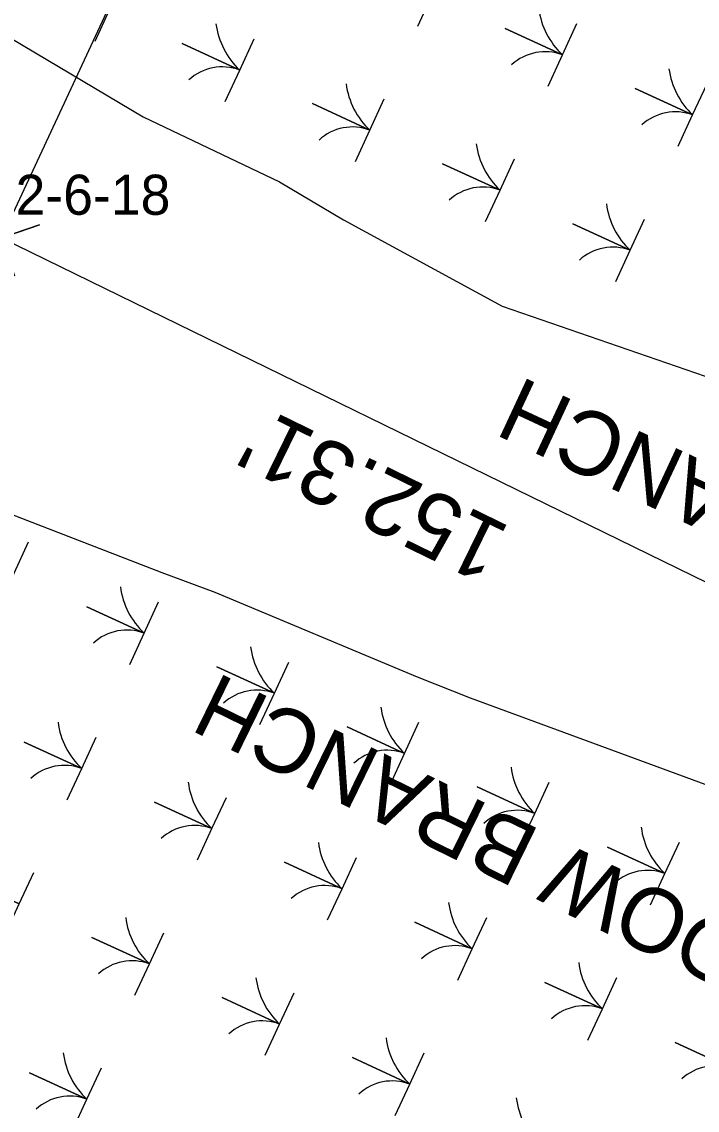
# Model space of a CAD drawing. Extents: x 2532037 to 2533565, y 713396 to 716867.
# Drawn here: x 2532899.5 to 2532941.6, y 715572.7 to 715640.6 of the extents above; entities that cross this region are included whole.
import ezdxf

# ---------------------------------------------------------------- set-up
doc = ezdxf.new("R2010")
doc.units = 0
for name, color, linetype in [('Exist DTM Spot Elevation Cogo Comment', 7, 'Continuous'), ('Exist Hydro Jurisdictional Stream or Body of Water', 7, 'Continuous'), ('Exist Hydro Stream or Body of Water Text', 7, 'Continuous'), ('Exist Property Corner CELL', 7, 'Continuous'), ('Exist Property Line', 7, 'Continuous'), ('Exist Property Line Text', 7, 'Continuous'), ('Exist Right of Way Line', 7, 'Continuous'), ('Scratch_Level_1', 7, 'Continuous')]:
    doc.layers.add(name, color=color, linetype=linetype)

msp = doc.modelspace()

# ---------------------------------------------------------------- linework, layer by layer
at = {"layer": 'Exist Hydro Jurisdictional Stream or Body of Water'}
for points in [[(2532806.944, 715649.86), (2532823.862, 715653.608), (2532826.936, 715654.78), (2532846.795, 715657.486), (2532848.935, 715657.763), (2532859.818, 715661.557), (2532865.255, 715655.34), (2532866.545, 715654.873), (2532867.828, 715654.527), (2532870.349, 715653.031), (2532883.272, 715647.025), (2532884.83, 715646.372), (2532885.882, 715645.762), (2532886.539, 715645.426), (2532889.693, 715644.068), (2532889.952, 715644.137), (2532891.522, 715643.982), (2532891.782, 715643.826), (2532896.496, 715640.921), (2532907.078, 715634.646), (2532915.587, 715630.595), (2532919.574, 715628.211), (2532929.47, 715622.835), (2532946.956, 715616.792)], [(2532799.821, 715621.688), (2532825.866, 715627.44), (2532828.419, 715628.003), (2532832.005, 715633.511), (2532832.017, 715633.527), (2532835.552, 715631.335), (2532845.081, 715630.726), (2532846.796, 715630.623), (2532853.018, 715629.166), (2532854.009, 715628.204), (2532858.784, 715626.141), (2532874.956, 715619.591), (2532887.027, 715614.556), (2532890.708, 715612.987), (2532908.235, 715606.211), (2532911.538, 715604.984), (2532924.18, 715599.711), (2532927.478, 715598.382), (2532943.534, 715592.488)]]:
    msp.add_lwpolyline(points, dxfattribs=at)
at = {"layer": 'Exist Property Corner CELL'}
msp.add_lwpolyline([(2532895.873, 715626.28), (2532900.602, 715627.904), (2532898.238, 715627.092), (2532897.425, 715629.457), (2532899.05, 715624.728)], dxfattribs=at)
at = {"layer": 'Exist Property Line'}
msp.add_line((2532898.238, 715627.092), (2533035.08, 715560.215), dxfattribs=at)
at = {"layer": 'Exist Right of Way Line'}
msp.add_line((2532748.017, 715304.207), (2532950.036, 715738.429), dxfattribs=at)
at = {"layer": 'Scratch_Level_1'}
for points in [[(2532924.214, 715640.31), (2532925.116, 715642.262), (2532921.534, 715643.916), (2532925.116, 715642.262), (2532926.017, 715644.215)], [(2532904.073, 715639.364), (2532904.974, 715641.317), (2532901.392, 715642.97), (2532904.974, 715641.317), (2532905.876, 715643.269)], [(2532932.336, 715636.561), (2532933.237, 715638.513), (2532929.655, 715640.167), (2532933.237, 715638.513), (2532934.138, 715640.465)], [(2532912.194, 715635.615), (2532913.096, 715637.567), (2532909.514, 715639.221), (2532913.096, 715637.567), (2532913.997, 715639.52)], [(2532940.457, 715632.811), (2532941.358, 715634.764), (2532937.777, 715636.417), (2532941.358, 715634.764), (2532942.26, 715636.716)], [(2532920.316, 715631.866), (2532921.217, 715633.818), (2532917.635, 715635.472), (2532921.217, 715633.818), (2532922.118, 715635.77)], [(2532928.437, 715628.116), (2532929.339, 715630.069), (2532925.757, 715631.722), (2532929.339, 715630.069), (2532930.24, 715632.021)], [(2532936.559, 715624.367), (2532937.46, 715626.319), (2532933.878, 715627.973), (2532937.46, 715626.319), (2532938.361, 715628.272)], [(2532898.117, 715604.22), (2532899.018, 715606.173), (2532895.436, 715607.826), (2532899.018, 715606.173), (2532899.92, 715608.125)], [(2532906.238, 715600.471), (2532907.14, 715602.423), (2532903.558, 715604.077), (2532907.14, 715602.423), (2532908.041, 715604.376)], [(2532914.36, 715596.721), (2532915.261, 715598.674), (2532911.679, 715600.327), (2532915.261, 715598.674), (2532916.163, 715600.626)], [(2532922.481, 715592.972), (2532923.383, 715594.924), (2532919.801, 715596.578), (2532923.383, 715594.924), (2532924.284, 715596.877)], [(2532902.34, 715592.026), (2532903.241, 715593.979), (2532899.659, 715595.632), (2532903.241, 715593.979), (2532904.143, 715595.931)], [(2532930.603, 715589.223), (2532931.504, 715591.175), (2532927.922, 715592.829), (2532931.504, 715591.175), (2532932.405, 715593.127)], [(2532910.461, 715588.277), (2532911.363, 715590.229), (2532907.781, 715591.883), (2532911.363, 715590.229), (2532912.264, 715592.182)], [(2532938.724, 715585.473), (2532939.626, 715587.426), (2532936.044, 715589.079), (2532939.626, 715587.426), (2532940.527, 715589.378)], [(2532918.583, 715584.528), (2532919.484, 715586.48), (2532915.902, 715588.134), (2532919.484, 715586.48), (2532920.386, 715588.432)], [(2532898.442, 715583.582), (2532899.343, 715585.534), (2532895.761, 715587.188), (2532899.343, 715585.534), (2532900.244, 715587.487)], [(2532926.704, 715580.778), (2532927.606, 715582.731), (2532924.024, 715584.384), (2532927.606, 715582.731), (2532928.507, 715584.683)], [(2532906.563, 715579.833), (2532907.464, 715581.785), (2532903.882, 715583.439), (2532907.464, 715581.785), (2532908.366, 715583.737)], [(2532934.826, 715577.029), (2532935.727, 715578.981), (2532932.145, 715580.635), (2532935.727, 715578.981), (2532936.628, 715580.934)], [(2532914.684, 715576.083), (2532915.586, 715578.036), (2532912.004, 715579.689), (2532915.586, 715578.036), (2532916.487, 715579.988)], [(2532942.947, 715573.28), (2532943.849, 715575.232), (2532940.267, 715576.886), (2532943.849, 715575.232), (2532944.75, 715577.184)], [(2532922.806, 715572.334), (2532923.707, 715574.286), (2532920.125, 715575.94), (2532923.707, 715574.286), (2532924.609, 715576.239)], [(2532902.665, 715571.388), (2532903.566, 715573.341), (2532899.984, 715574.994), (2532903.566, 715573.341), (2532904.467, 715575.293)]]:
    msp.add_lwpolyline(points, dxfattribs=at)
for centre, radius, start, end in [((2532936.524, 715642.018), 4.806, 187.34643, 226.84116), ((2532916.383, 715641.073), 4.806, 187.34643, 226.84116), ((2532932.153, 715635.636), 3.075, 69.35932, 132.75394), ((2532912.012, 715634.69), 3.075, 69.35932, 132.75394), ((2532944.646, 715638.269), 4.806, 187.34643, 226.84116), ((2532924.504, 715637.323), 4.806, 187.34643, 226.84116), ((2532940.275, 715631.886), 3.075, 69.35932, 132.75394), ((2532920.133, 715630.941), 3.075, 69.35932, 132.75394), ((2532932.626, 715633.574), 4.806, 187.34643, 226.84116), ((2532928.255, 715627.191), 3.075, 69.35932, 132.75394), ((2532940.747, 715629.825), 4.806, 187.34643, 226.84116), ((2532936.376, 715623.442), 3.075, 69.35932, 132.75394), ((2532910.427, 715605.929), 4.806, 187.34643, 226.84116), ((2532906.056, 715599.546), 3.075, 69.35932, 132.75394), ((2532918.548, 715602.179), 4.806, 187.34643, 226.84116), ((2532914.177, 715595.797), 3.075, 69.35932, 132.75394), ((2532926.67, 715598.43), 4.806, 187.34643, 226.84116), ((2532906.529, 715597.484), 4.806, 187.34643, 226.84116), ((2532922.299, 715592.047), 3.075, 69.35932, 132.75394), ((2532902.158, 715591.102), 3.075, 69.35932, 132.75394), ((2532934.791, 715594.681), 4.806, 187.34643, 226.84116), ((2532914.65, 715593.735), 4.806, 187.34643, 226.84116), ((2532930.42, 715588.298), 3.075, 69.35932, 132.75394), ((2532910.279, 715587.352), 3.075, 69.35932, 132.75394), ((2532942.913, 715590.931), 4.806, 187.34643, 226.84116), ((2532922.771, 715589.986), 4.806, 187.34643, 226.84116), ((2532938.542, 715584.548), 3.075, 69.35932, 132.75394), ((2532918.4, 715583.603), 3.075, 69.35932, 132.75394), ((2532930.893, 715586.236), 4.806, 187.34643, 226.84116), ((2532910.752, 715585.291), 4.806, 187.34643, 226.84116), ((2532926.522, 715579.853), 3.075, 69.35932, 132.75394), ((2532906.381, 715578.908), 3.075, 69.35932, 132.75394), ((2532939.014, 715582.487), 4.806, 187.34643, 226.84116), ((2532918.873, 715581.541), 4.806, 187.34643, 226.84116), ((2532934.643, 715576.104), 3.075, 69.35932, 132.75394), ((2532914.502, 715575.158), 3.075, 69.35932, 132.75394), ((2532926.994, 715577.792), 4.806, 187.34643, 226.84116), ((2532906.853, 715576.846), 4.806, 187.34643, 226.84116), ((2532942.765, 715572.355), 3.075, 69.35932, 132.75394), ((2532922.623, 715571.409), 3.075, 69.35932, 132.75394), ((2532902.482, 715570.463), 3.075, 69.35932, 132.75394), ((2532935.116, 715574.042), 4.806, 187.34643, 226.84116)]:
    msp.add_arc(centre, radius, start, end, dxfattribs=at)

# ---------------------------------------------------------------- texts
at = {"layer": 'Exist DTM Spot Elevation Cogo Comment'}
msp.add_text("TOP OF WATER EL: 18.65' @ 11:22 AM, 12-6-18", height=2.5, dxfattribs=at).set_placement((2532834.511, 715628.536))
at = {"layer": 'Exist Hydro Stream or Body of Water Text'}
msp.add_text('MEADOW BRANCH', height=4, rotation=155.05, dxfattribs=at).set_placement((2532974.808, 715597.932))
at = {"layer": 'Exist Property Line Text'}
for s, p in [("152.31'", (2532930.101, 715609.004)), ('PROPERTY LINE RUNS THE CENTER OF MEADOW BRANCH', (2533050.265, 715532.289))]:
    msp.add_text(s, height=4, rotation=153.95434, dxfattribs=at).set_placement(p)

doc.saveas('drawing.dxf')
